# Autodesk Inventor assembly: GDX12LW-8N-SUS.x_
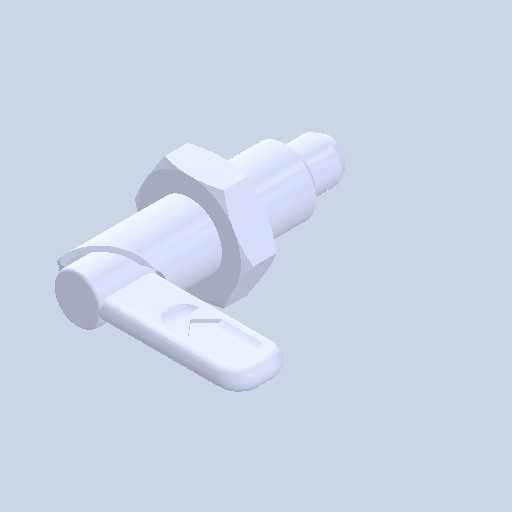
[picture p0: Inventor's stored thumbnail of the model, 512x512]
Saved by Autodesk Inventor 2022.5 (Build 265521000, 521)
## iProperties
Created: 2024-06
Part Number: GDX12LW-8N-SUS.x_
Document SubType Name: Assembly
Designer: ImaoCorp
Author: ImaoCorp
Sending System: SOLIDWORKS 2022-2022290
MC: AMD64
MC_MODEL: Intel64 Family 6 Model 60 Stepping 3, GenuineIntel
OS: Windows_NT
FRU: Parasolid Version 33.1, build 260,  4-25-2022
FORMAT: text
GUISE: transmit
KEY: FILEGDX12LW-8N-SUS.x_t
DATE: Wed Jun 12 09:32:09 2024
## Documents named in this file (4)
- Y:\5.更新分\2024年対応\xxxx_GDX\データ_imao品番\gdx12lw-8n-sus\GDX12LW-8N-SUS.x_.iam
- Y:\5.更新分\2024年対応\xxxx_GDX\データ_imao品番\gdx12lw-8n-sus\GDX12LW-8N-SUS_01.ipt
- Y:\5.更新分\2024年対応\xxxx_GDX\データ_imao品番\gdx12lw-8n-sus\GDX12LW-8N-SUS_02.ipt
- Y:\5.更新分\2024年対応\xxxx_GDX\データ_imao品番\gdx12lw-8n-sus\GDX12LW-8N-SUS_03.ipt
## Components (3 placed, 3 different names)
1. GDX12LW-8N-SUS_01
2. GDX12LW-8N-SUS_02
3. GDX12LW-8N-SUS_03
